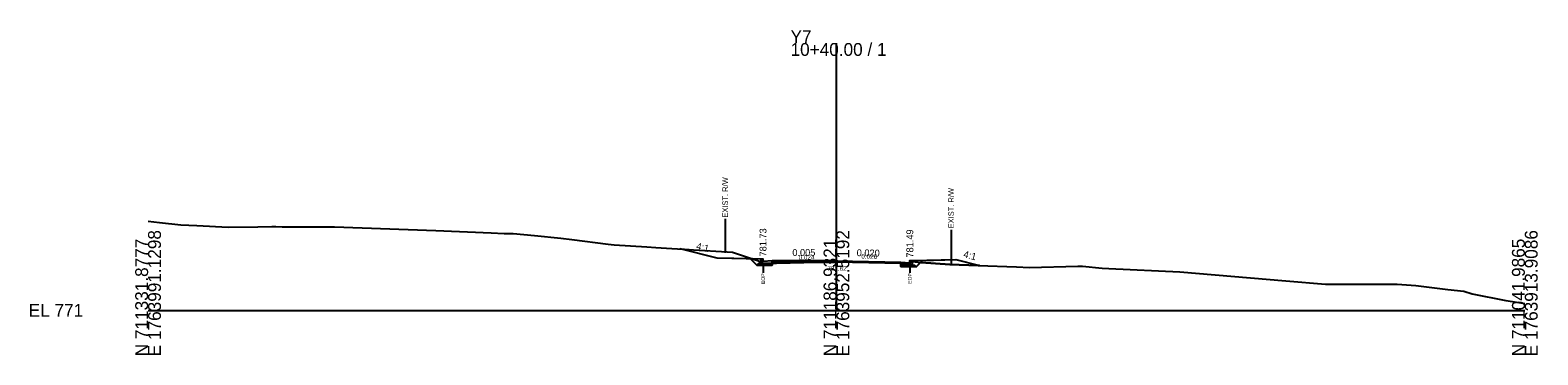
# Model space of a CAD drawing. Extents: x -26 to 2903, y -10 to 1056.
# Drawn here: x 2574.3 to 2902.8, y -9.7 to 61 of the extents above; entities that cross this region are included whole.
import ezdxf

# ---------------------------------------------------------------- set-up
doc = ezdxf.new("R2010")
doc.units = 0
for name, color, linetype in [('Exist CMT Pavement', 7, 'Continuous'), ('Exist Cross Section Cell', 7, 'Continuous'), ('Exist XS Center Line Elevation Label', 7, 'Continuous'), ('Exist XS Ground Line', 7, 'Continuous'), ('Old_Level_10', 7, 'Continuous'), ('Prop CMT Conc Surface', 7, 'Continuous'), ('Prop CMT Concrete Structures', 7, 'Continuous'), ('Prop CMT Pvmt Course 1', 7, 'Continuous'), ('Prop CMT Pvmt Course 1 CG', 7, 'Continuous'), ('Prop CMT Pvmt Course 2', 7, 'Continuous'), ('Prop CMT Pvmt Course 3', 7, 'Continuous'), ('Prop CMT Pvmt Surface', 7, 'Continuous'), ('Prop CMT Slope Grass', 7, 'Continuous'), ('Prop CMT Subgrade Earthwork', 7, 'Continuous'), ('Prop XS Earthwork Shape', 7, 'Continuous'), ('Prop XS Hydro Elevations', 7, 'Continuous'), ('Prop XS SE Text', 7, 'Continuous'), ('Prop XS Side Slope Text', 7, 'Continuous'), ('Prop XS Wedging', 7, 'Continuous'), ('Scratch_Level_1', 7, 'Continuous')]:
    doc.layers.add(name, color=color, linetype=linetype)

msp = doc.modelspace()

# ---------------------------------------------------------------- linework, layer by layer
at = {"layer": 'Exist CMT Pavement'}
msp.add_lwpolyline([(2736, 10.28), (2748.83, 10.6), (2750, 10.62), (2751.4, 10.65), (2764, 10.32)], dxfattribs=at)
at = {"layer": 'Exist Cross Section Cell'}
for p, q in [((2750, 0), (2750, 58.23)), ((2600, 0), (2750, 0)), ((2750, 0), (2900, 0))]:
    msp.add_line(p, q, dxfattribs=at)
at = {"layer": 'Exist XS Ground Line'}
msp.add_lwpolyline([(2600, 19.41), (2602.47, 19.13), (2607.11, 18.62), (2610.64, 18.46), (2617.46, 18.12), (2623.89, 18.17), (2626.99, 18.27), (2627.81, 18.23), (2629.24, 18.22), (2640.59, 18.16), (2662.74, 17.38), (2674.76, 16.88), (2677.59, 16.73), (2679.56, 16.74), (2684.2, 16.32), (2689.91, 15.7), (2692.37, 15.41), (2700.26, 14.39), (2701.6, 14.3), (2708.72, 13.81), (2710.61, 13.67), (2718.82, 13.21), (2726.2, 12.76), (2727.36, 12.7), (2729.95, 11.78), (2733.46, 10.65), (2733.98, 10.23), (2748.83, 10.6), (2750, 10.62), (2751.4, 10.65), (2764.27, 10.31), (2766.02, 10.27), (2766.56, 10.65), (2768.46, 10.42), (2774.68, 9.96), (2780.87, 9.75), (2789.25, 9.49), (2792.04, 9.32), (2802.61, 9.63), (2802.96, 9.63), (2803.62, 9.63), (2807.9, 9.19), (2809.36, 9.11), (2824.8, 8.41), (2847.93, 6.4), (2856.56, 5.7), (2857.73, 5.69), (2872.18, 5.71), (2876.22, 5.4), (2883.19, 4.55), (2886.7, 4.18), (2888.52, 3.59), (2895.87, 2.17), (2897.3, 1.91), (2900, 1.48)], dxfattribs=at)
at = {"layer": 'Old_Level_10'}
for p, q in [((2725.75, 19.9), (2725.75, 12.5)), ((2774.98, 17.56), (2774.98, 10.16)), ((2734.01, 10.2), (2734.01, 8.15)), ((2766, 10.24), (2766, 8.19))]:
    msp.add_line(p, q, dxfattribs=at)
at = {"layer": 'Prop CMT Conc Surface'}
for points in [[(2734, 10.67), (2734, 11.17), (2733.5, 11.17)], [(2736, 10.75), (2734, 10.67)], [(2764, 10.47), (2766, 10.35)], [(2766, 10.35), (2766, 10.85), (2766.5, 10.85)]]:
    msp.add_lwpolyline(points, dxfattribs=at)
at = {"layer": 'Prop CMT Concrete Structures'}
for points in [[(2736, 10.75), (2734, 10.67), (2734, 11.17), (2733.5, 11.17)], [(2733.5, 11.17), (2733.5, 10.17), (2736, 10.17)], [(2736, 10.17), (2736, 10.75)], [(2764, 10.47), (2766, 10.35), (2766, 10.85), (2766.5, 10.85)], [(2766.5, 10.85), (2766.5, 9.84), (2764, 9.89)], [(2764, 9.89), (2764, 10.47)]]:
    msp.add_lwpolyline(points, dxfattribs=at)
at = {"layer": 'Prop CMT Pvmt Course 1'}
for p, q in [((2744.85, 10.5), (2736.35, 10.5)), ((2736.35, 10.5), (2736.55, 10.3)), ((2736.55, 10.3), (2744.85, 10.5))]:
    msp.add_line(p, q, dxfattribs=at)
for points in [[(2736, 10.5), (2735.98, 10.5)], [(2735.98, 10.5), (2735.98, 10.5)], [(2735.98, 10.5), (2750, 10.5)], [(2750, 10.75), (2736, 10.75)], [(2736, 10.75), (2736, 10.5)], [(2750, 10.5), (2750, 10.75)], [(2750, 10.75), (2764, 10.47)], [(2750, 10.5), (2750, 10.5), (2750, 10.5)], [(2764.02, 10.22), (2750, 10.5)], [(2764, 10.47), (2764, 10.22)], [(2764, 10.22), (2764.02, 10.22)], [(2764.02, 10.22), (2764.02, 10.22)]]:
    msp.add_lwpolyline(points, dxfattribs=at)
at = {"layer": 'Prop CMT Pvmt Course 1 CG'}
for points in [[(2736, 10.17), (2733, 10.17), (2732.67, 9.83)], [(2736, 9.83), (2736, 10.17)], [(2764, 9.89), (2767, 9.83), (2767.34, 9.49)], [(2764, 9.55), (2764, 9.89)], [(2732.67, 9.83), (2736, 9.83)], [(2767.34, 9.49), (2764, 9.55)]]:
    msp.add_lwpolyline(points, dxfattribs=at)
at = {"layer": 'Prop CMT Pvmt Course 2'}
for points in [[(2735.98, 10.17), (2735.98, 10.5)], [(2735.98, 10.5), (2736, 10.5)], [(2736, 10.17), (2735.98, 10.17)], [(2736, 10.5), (2736, 10.17)], [(2764.02, 10.22), (2764, 10.22)], [(2764, 10.22), (2764, 9.89)], [(2764, 9.89), (2764.02, 9.89)], [(2764.02, 9.89), (2764.02, 10.22)]]:
    msp.add_lwpolyline(points, dxfattribs=at)
at = {"layer": 'Prop CMT Pvmt Course 3'}
for points in [[(2735.98, 10.17), (2736, 10.17)], [(2735.98, 9.83), (2735.98, 10.17)], [(2736, 10.17), (2736, 9.83)], [(2764.02, 9.89), (2764, 9.89)], [(2764, 9.89), (2764, 9.55)], [(2764.02, 9.55), (2764.02, 9.89)], [(2736, 9.83), (2735.98, 9.83)], [(2764, 9.55), (2764.02, 9.55)]]:
    msp.add_lwpolyline(points, dxfattribs=at)
at = {"layer": 'Prop CMT Pvmt Surface'}
for points in [[(2750, 10.75), (2736, 10.75)], [(2750, 10.75), (2764, 10.47)]]:
    msp.add_lwpolyline(points, dxfattribs=at)
at = {"layer": 'Prop CMT Slope Grass'}
for points in [[(2733.5, 11.17), (2724, 11.36), (2715.96, 13.37)], [(2766.5, 10.85), (2776, 11.04), (2781.19, 9.74)]]:
    msp.add_lwpolyline(points, dxfattribs=at)
at = {"layer": 'Prop CMT Subgrade Earthwork'}
for p, q in [((2736, 9.83), (2736, 10.28)), ((2764, 9.55), (2764, 10.32))]:
    msp.add_line(p, q, dxfattribs=at)
for points in [[(2736, 9.83), (2732.67, 9.83), (2731.29, 11.21)], [(2764, 9.55), (2767.34, 9.49), (2768.75, 10.89)]]:
    msp.add_lwpolyline(points, dxfattribs=at)
at = {"layer": 'Prop XS Earthwork Shape'}
for points in [[(2731.73, 11.21), (2731.29, 11.21), (2724, 11.36), (2715.96, 13.37), (2718.82, 13.21), (2726.2, 12.76), (2727.36, 12.7), (2729.95, 11.78)], [(2731.73, 11.21), (2733.46, 10.65), (2733.98, 10.23), (2736, 10.28), (2736, 9.83), (2732.67, 9.83), (2731.29, 11.21)], [(2766.02, 10.27), (2766.56, 10.65), (2768.3, 10.44), (2767.34, 9.49), (2764, 9.55), (2764, 10.32), (2764.27, 10.31)], [(2768.3, 10.44), (2768.75, 10.89), (2776, 11.04), (2781.19, 9.74), (2780.87, 9.75), (2774.68, 9.96), (2768.46, 10.42)]]:
    msp.add_lwpolyline(points, close=True, dxfattribs=at)
at = {"layer": 'Prop XS Wedging'}
for p, q in [((2736.35, 10.5), (2736, 10.5)), ((2736, 10.5), (2736, 10.28)), ((2736, 10.28), (2736.55, 10.3)), ((2736.35, 10.5), (2736.35, 10.5)), ((2736.55, 10.3), (2736.35, 10.5))]:
    msp.add_line(p, q, dxfattribs=at)
at = {"layer": 'Scratch_Level_1'}
for p, q in [((2733.98, 10.23), (2751.4, 10.65)), ((2751.4, 10.65), (2764.27, 10.31))]:
    msp.add_line(p, q, dxfattribs=at)

# ---------------------------------------------------------------- texts
at = {"layer": 'Exist Cross Section Cell'}
for s, p in [('Y7', (2740, 58.23)), ('10+40.00 / 1', (2740, 55.43)), ('EL 771', (2574, -1.4))]:
    msp.add_text(s, height=2.8, dxfattribs=at).set_placement(p)
for s, p in [('E 1763991.1298', (2602.8, -10)), ('E 1763952.5192', (2752.8, -10)), ('E 1763913.9086', (2902.8, -10)), ('N 711331.8777', (2600, -10)), ('N 711186.9321', (2750, -10)), ('N 711041.9865', (2900, -10))]:
    msp.add_text(s, height=2.8, rotation=90, dxfattribs=at).set_placement(p)
at = {"layer": 'Exist XS Center Line Elevation Label'}
msp.add_text('781.62', height=1, dxfattribs=at).set_placement((2748.01, 8.62))
at = {"layer": 'Old_Level_10'}
for s, height, p in [('EXIST. R/W', 1.181, (2726.34, 20.2)), ('EXIST. R/W', 1.181, (2775.57, 17.86)), ('EOP', 0.787, (2734.4, 5.75)), ('EOP', 0.787, (2766.39, 5.79))]:
    msp.add_text(s, height=height, rotation=90, dxfattribs=at).set_placement(p)
at = {"layer": 'Prop XS Hydro Elevations'}
for s, p in [('781.73', (2734.75, 11.73)), ('781.49', (2766.75, 11.49))]:
    msp.add_text(s, height=1.5, rotation=90, dxfattribs=at).set_placement(p)
at = {"layer": 'Prop XS SE Text'}
for s, rotation, p in [('0.005', 0.2934, (2740.39, 11.84)), ('0.020', 358.8542, (2754.4, 11.81))]:
    msp.add_text(s, height=1.5, rotation=rotation, dxfattribs=at).set_placement(p)
at = {"layer": 'Prop XS Side Slope Text'}
for p in [(2719.33, 13.36), (2777.57, 11.56)]:
    msp.add_text('4:1', height=1.5, rotation=345.9638, dxfattribs=at).set_placement(p)
at = {"layer": 'Scratch_Level_1'}
for s, rotation, p in [('0.024', 1.37, (2741.77, 11)), ('0.026', 358.5025, (2755.41, 11.29))]:
    msp.add_text(s, height=1, rotation=rotation, dxfattribs=at).set_placement(p)

doc.saveas('drawing.dxf')
